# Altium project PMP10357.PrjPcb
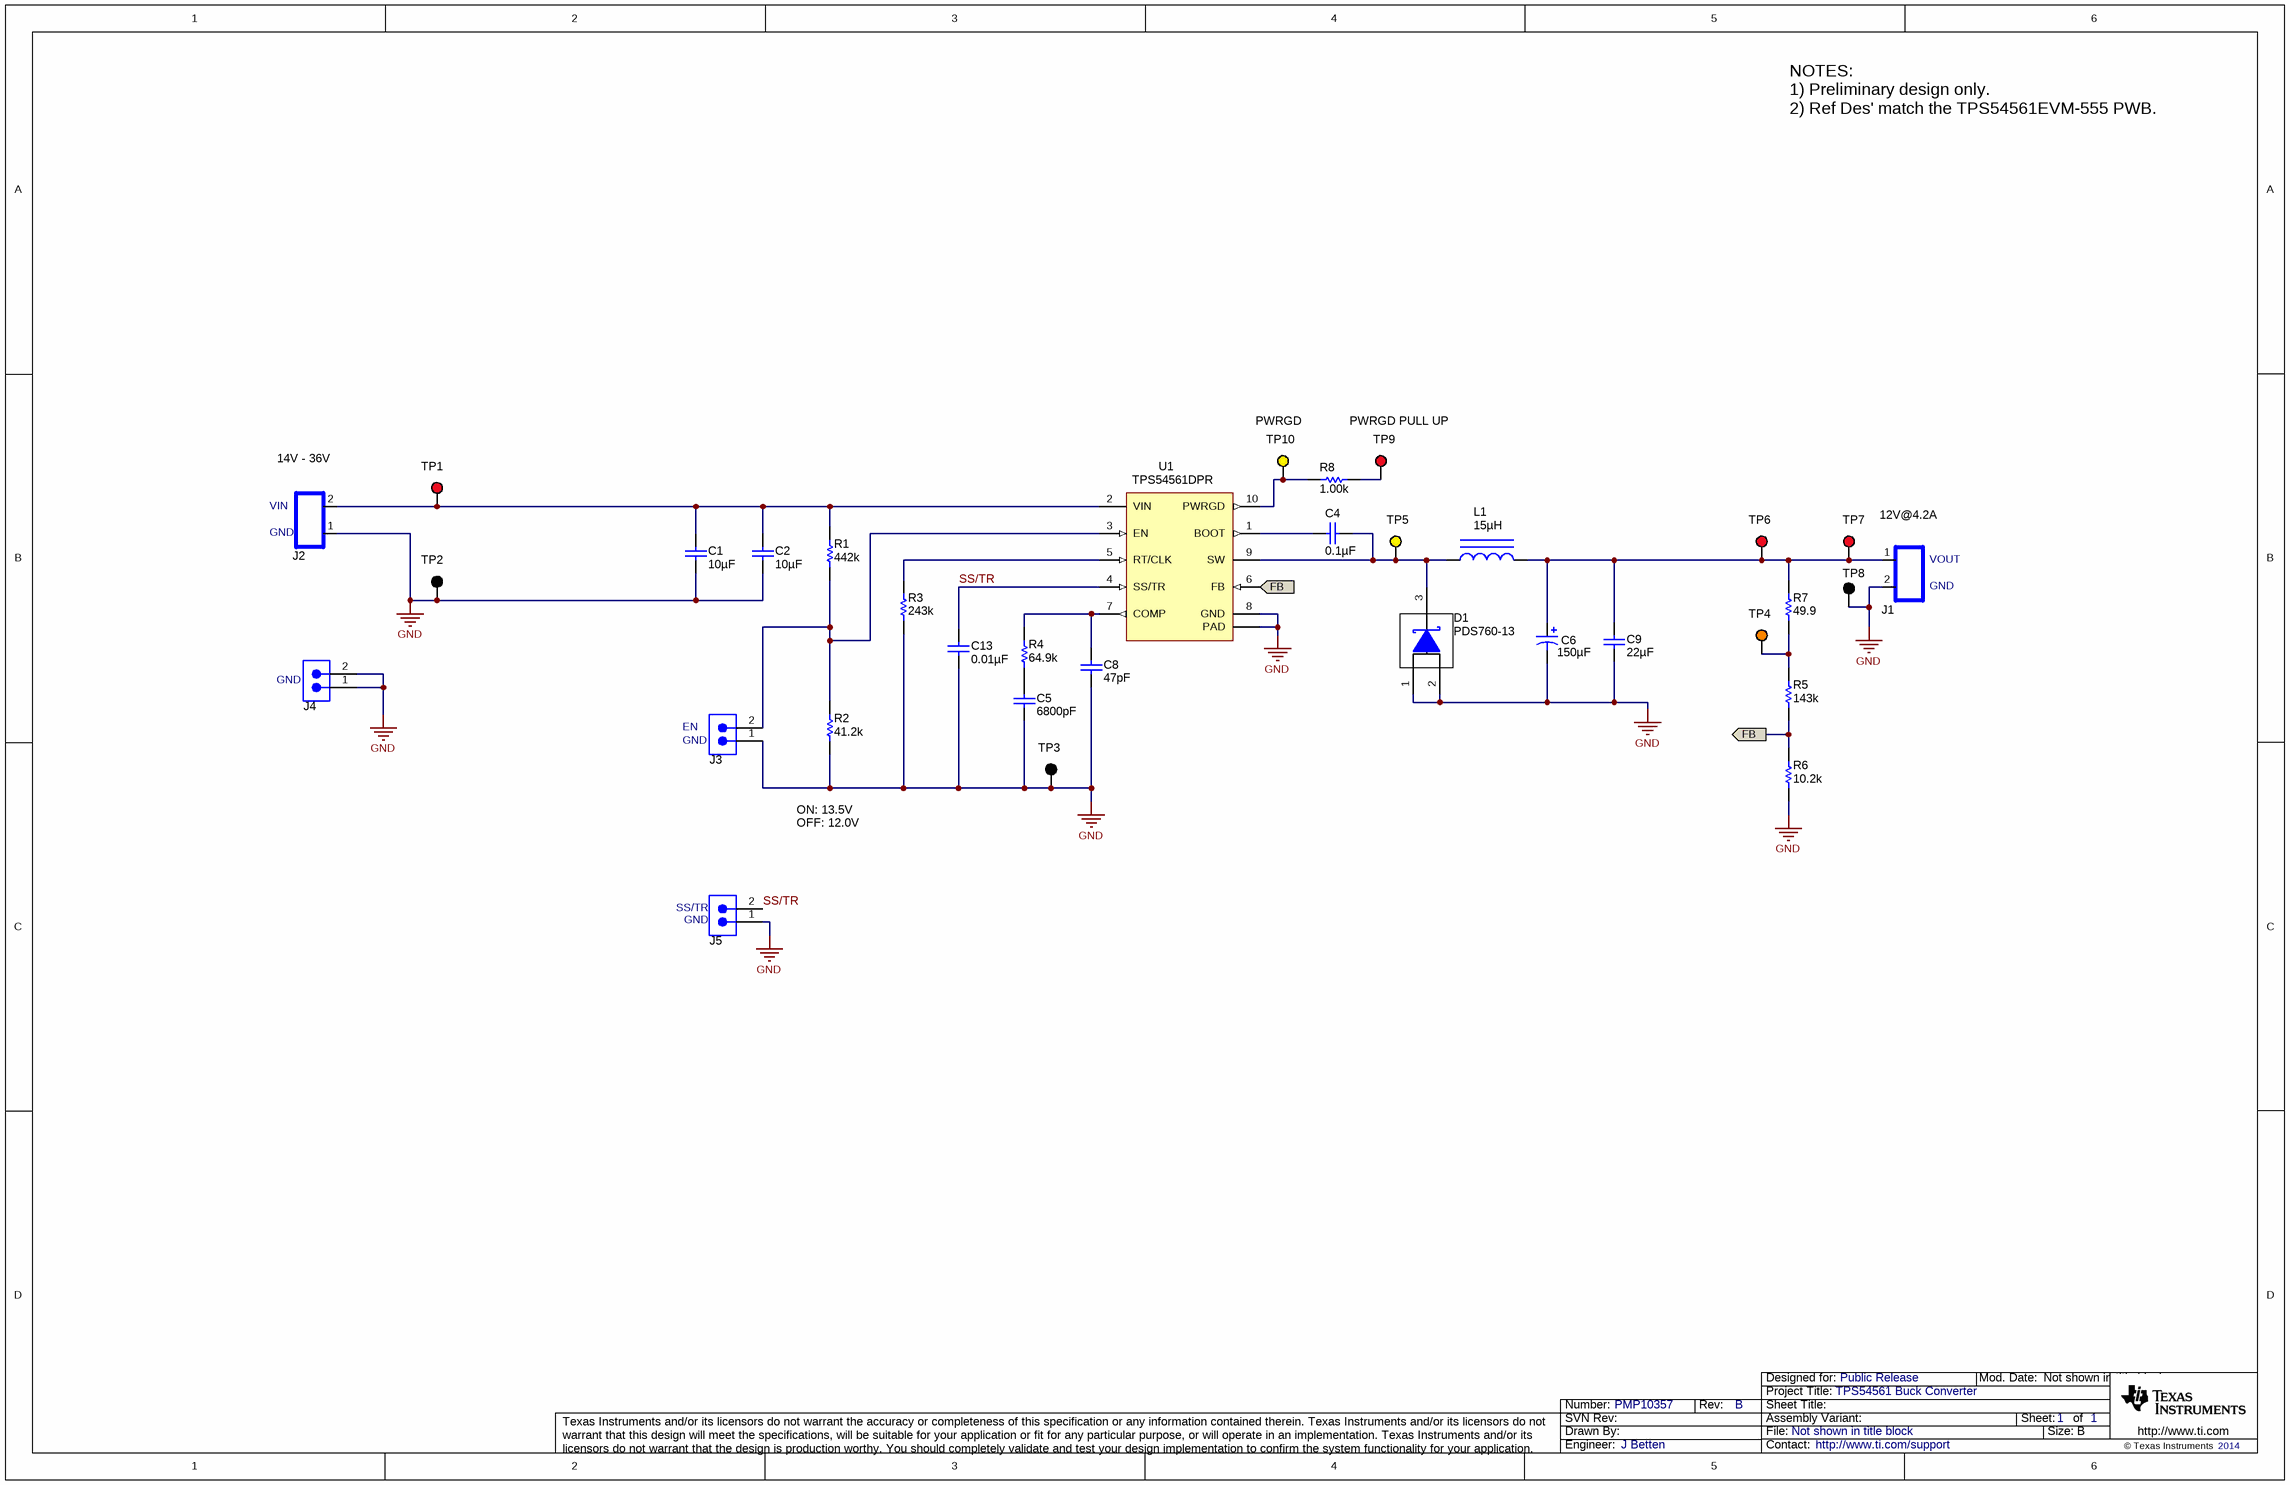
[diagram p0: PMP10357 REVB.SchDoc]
TechSupport: http://www.ti.com/support; SCH_Rev: B; PRJ_Title: TPS54561 Buck Converter; PRJ_Number: PMP10357; PRJ_Engineer: J Betten; PRJ_Customer: Public Release; PCB_Rev: A; PCB_Layout: J Betten; CopyrightYear: 2014
1 sheet, 34 parts. Net scope: flat (ports and power ports of the same name join across sheets).
Board file: PWR555A_pcb_ASCII.PcbDoc

## Sheet PMP10357 REVB.SchDoc
size 431 x 279 mm; Date: Not shown in title block; ApprovedBy: Not shown in title block; CheckedBy: Not shown in title block; Author: Not shown in title block; CompanyName: Not shown in title block; Engineer: Not shown in title block; Organization: Not shown in title block; Address1: Not shown in title block; Address2: Not shown in title block; Address3: Not shown in title block; Address4: Not shown in title block; DocumentNumber: 1; Revision: Use project parameter SCH_Rev; SheetNumber: 1; SheetTotal: 1; PageSetup: Record=PageOptions|CenterHorizontal=True|CenterVertical=True|PrintScale=1.00|XCorrection=1.00|YCorrection=1.00|PrintKind=0|BorderSize=5000000|LeftOffset=0|BottomOffset=0|Orientation=2|PaperLength=1000|PaperWidth=1000|Scale=100|PaperSource=15|PrintQuality=600|MediaType=1|DitherType=10|PaperKind=Letter|PrintScaleMode=1

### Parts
C1  ValueDisplayed: 10µF  [1210]  (hidden comment: C3225X7R1H106M250AC)
C2  ValueDisplayed: 10µF  [1210]  (hidden comment: C3225X7R1H106M250AC)
C4  ValueDisplayed: 0.1µF  [0603]  (hidden comment: C0603C104K8RACTU)
C5  ValueDisplayed: 6800pF  [0603]  (hidden comment: C1608C0G1H682J)
C6  ValueDisplayed: 150µF  [7343-20]  (hidden comment: 16TQC150MYF)
C8  ValueDisplayed: 47pF  [0603]  (hidden comment: C1608C0G1H470J)
C9  ValueDisplayed: 22µF  [1210]  (hidden comment: C3225X7R1C226M250AC)
C13  ValueDisplayed: 0.01µF  [0603]  (hidden comment: C0603C103K5RACTU)
D1  PDS760-13  [PowerDI5]
J1  TBLK_15A_2X5.1MM  [TB_2X5.1MM]  (value not drawn)
J2  TBLK_15A_2X5.1MM  [TB_2X5.1MM]  (value not drawn)
J3  TSW-102-07-G-S  [TSW-102-07-G-S]  (value not drawn)
J4  TSW-102-07-G-S  [TSW-102-07-G-S]  (value not drawn)
J5  TSW-102-07-G-S  [TSW-102-07-G-S]  (value not drawn)
L1  ValueDisplayed: 15µH  [XAL1010]  (hidden comment: XAL1010-153MEB)
R1  value 442k  [0603]  (hidden comment: CRCW0603442KFKEA)
R2  value 41.2k  [0603]  (hidden comment: CRCW060341K2FKEA)
R3  value 243k  [0603]  (hidden comment: CRCW0603243KFKEA)
R4  value 64.9k  [0603]  (hidden comment: CRCW060364K9FKEA)
R5  value 143k  [0603]  (hidden comment: CRCW0603143KFKEA)
R6  value 10.2k  [0603]  (hidden comment: CRCW060310K2FKEA)
R7  value 49.9  [0603]  (hidden comment: CRCW060349R9FKEA)
R8  value 1.00k  [0603]  (hidden comment: CRCW06031K00FKEA)
TP1  5010  [Keystone5010]  (value not drawn)
TP2  5011  [Keystone5011]  (value not drawn)
TP3  5011  [Keystone5011]  (value not drawn)
TP4  5013  [Keystone5013]  (value not drawn)
TP5  5014  [Keystone5014]  (value not drawn)
TP6  5010  [Keystone5010]  (value not drawn)
TP7  5010  [Keystone5010]  (value not drawn)
TP8  5011  [Keystone5011]  (value not drawn)
TP9  5010  [Keystone5010]  (value not drawn)
TP10  5014  [Keystone5014]  (value not drawn)
U1  TPS54561DPR  [DPR0010A]

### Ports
FB (in), FB (out)

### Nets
GND: C1.2 C2.2 C5.2 C6.2(-) C8.2 C9.2 C13.2 D1.1(A) D1.2(A) J1.2 J2.1 J3.1 J4.1 J4.2 J5.1 R2.1 R3.1 R6.1 TP2.1 TP3.1 TP8.1 U1.8(GND) U1.11(PAD)
FB: R5.1 R6.2 U1.6(FB) ; port FB
SS/TR: C13.1 J5.2 U1.4(SS/TR)
NetC1_1: C1.1 C2.1 J2.2 R1.2 TP1.1 U1.2(VIN)
NetC4_1: C4.1 D1.3(K) L1.1 TP5.1 U1.9(SW)
NetC4_2: C4.2 U1.1(BOOT)
NetC5_1: C5.1 R4.1
NetC6_1: C6.1(+) C9.1 J1.1 L1.2 R7.2 TP6.1 TP7.1
NetC8_1: C8.1 R4.2 U1.7(COMP)
NetJ3_2: J3.2 R1.1 R2.2 U1.3(EN)
NetR3_2: R3.2 U1.5(RT/CLK)
NetR5_2: R5.2 R7.1 TP4.1
NetR8_1: R8.1 TP10.1 U1.10(PWRGD)
NetR8_2: R8.2 TP9.1

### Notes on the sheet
- NOTES:
  1) Preliminary design only.
  2) Ref Des' match the TPS54561EVM-555 PWB.
- PWRGD
- PWRGD PULL UP
- (near J2) 14V - 36V
- (near J2) VIN
- (near J2) GND
- 12V@4.2A
- (near J1) VOUT
- (near J1) GND
- (near J4) GND
- (near J3) EN
- (near J3) GND
- ON: 13.5V
- OFF: 12.0V
- (near J5) SS/TR
- (near J5) GND

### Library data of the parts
C1 C2 = GRM32ER72A225KA35L: CAP, CERM, 10uF, 50V, +/-10%, X7R, 1210; Manufacturer: TDK; Polarized: N; CompType: Capacitor; U/M: EA; Cap_F: 0.0000022; Tolerance_%: 10; ESR_Ohm: 0.007; Value1: 0.007 ohm; VDC_V: 50; IRMS_A: 4.4; TaMin_C: -55; TaMax_C: 125
C4 = C0603C104K8RACTU: CAP, CERM, 0.1uF, 10V, +/-10%, X7R, 0603; Manufacturer: Kemet; Polarized: N; CompType: Capacitor; U/M: EA; Cap_F: 0.0000001; Tolerance_%: 10; TaMin_C: -55; TaMax_C: 125
C5 = C1608C0G1H332J: CAP, CERM, 6800pF, 50V, +/-5%, C0G/NP0, 0603; Manufacturer: TDK; Polarized: N; CompType: Capacitor; U/M: EA; Cap_F: 0.0000000033; Tolerance_%: 5; ESR_Ohm: 0.0309; Value1: 0.0309 ohm; VDC_V: 50; TaMin_C: -55; TaMax_C: 125
C6 = 6TPE470MAZU: CAP, TQC, 150uF, 16V, +/-10%, 0.05 ohm, SMD; Manufacturer: Sanyo; Polarized: Y; CompType: Capacitor; U/M: EA; Cap_F: 0.00047; Tolerance_%: 10; VDC_V: 16; ESR_Ohm: 0.035; IRMS_A: 1.7; TaMin_C: -55; TaMax_C: 105; Cap_Case: D
C8 = C1608C0G1H470J: CAP, CERM, 47 pF, 50 V, +/- 5%, C0G/NP0, 0603; Manufacturer: TDK; Polarized: N; CompType: Capacitor; Value: 47pF; U/M: EA; Cap_F: 0.000000000047; Tolerance_%: 5; ESR_ohm: 0.22; Value1: 0.22 ohm; VDC_V: 50; Value2: 50V; TaMin_C: -55; TaMax_C: 125
C9 = GRM32ER61C476ME15L: CAP, CERM, 22uF, 16V, +/-20%, X7R, 1210; Manufacturer: TDK; Polarized: N; CompType: Capacitor; U/M: EA; Cap_F: 0.000047; Tolerance_%: 20; ESR_Ohm: 0.002; Value1: 0.002 ohm; VDC_V: 16; TaMin_C: -55; TaMax_C: 85
C13 = C0603C103K5RACTU: CAP, CERM, 0.01uF, 50V, +/-10%, X7R, 0603; Manufacturer: Kemet; Polarized: N; CompType: Capacitor; U/M: EA; Cap_F: 0.00000001; Tolerance_%: 10; Value1: Unknown; VDC_V: 50; TaMin_C: -55; TaMax_C: 125
D1 = PDS560-13: Diode, Schottky, 60V, 7A, PowerDI5; Manufacturer: Diodes Inc.; U/M: EA; Vf_V: 0.56; Io_A: 7; Vr_V: 60; Value2: 0.56V; TJmax_C: 150
J1 J2 = TBLK_15A_2X5.1MM: Terminal Block, 2-pin, 15-A, 5.1mm; Manufacturer: OST; PartNumber: ED120/2DS; Alternate Manufacturer: Any; Alternate PartNumber: Equivalent; area: 141600; Value: ED120/2DS
J3-J5 = TSW-102-07-G-S: Header, TH, 100mil, 2x1, Gold plated, 230 mil above insulator; Manufacturer: Samtec, Inc.; U/M: EA
L1 = XAL1010-153MEB: Inductor, Shielded, Composite, 15uH, 13.8A, 0.0169 ohm, SMD; Manufacturer: Coilcraft; Ind_H: 15.0E-6; Imax_A: 13.8; Irms: 13.8A @ 40C rise; Isat: 15.5A @ 30% inductance drop; DCR_ohm: 0.02
R1 = CRCW0603442KFKEA: RES, 442k ohm, 1%, 0.1W, 0603; Manufacturer: Vishay-Dale; Alternate Manufacturer: Any; Alternate PartNumber: Equivalent; CompType: Resistor; Res_ohm: 442000; Tolerance_%: 1; Power_W: 0.1; VDC_V: 75; TempCo: 100 ppm/C; EIA_Code: E96; U/M: EA
R2 = CRCW060341K2FKEA: RES, 41.2k ohm, 1%, 0.1W, 0603; Manufacturer: Vishay-Dale; CompType: Resistor; Res_ohm: 41200; Value_Code: 41k2; Tolerance_%: 1; Power_W: 0.1; VDC_V: 75; TempCo: 100 ppm/C; EIA_Code: E96; U/M: EA
R3 = CRCW0603243KFKEA: RES, 243k ohm, 1%, 0.1W, 0603; Manufacturer: Vishay-Dale; Alternate Manufacturer: Any; Alternate PartNumber: Equivalent; CompType: Resistor; Res_ohm: 243000; Tolerance_%: 1; Power_W: 0.1; VDC_V: 75; TempCo: 100 ppm/C; EIA_Code: E96; U/M: EA
R4 = CRCW060364K9FKEA: RES, 64.9k ohm, 1%, 0.1W, 0603; Manufacturer: Vishay-Dale; CompType: Resistor; Res_ohm: 64900; Value_Code: 64k9; Tolerance_%: 1; Power_W: 0.1; VDC_V: 75; TempCo: 100 ppm/C; EIA_Code: E96; U/M: EA
R5 = CRCW0603143KFKEA: RES, 143k ohm, 1%, 0.1W, 0603; Manufacturer: Vishay-Dale; CompType: Resistor; Res_ohm: 143000; Tolerance_%: 1; Power_W: 0.1; VDC_V: 75; TempCo: 100 ppm/C; EIA_Code: E96; U/M: EA
R6 = CRCW060310K2FKEA: RES, 10.2k ohm, 1%, 0.1W, 0603; Manufacturer: Vishay-Dale; Alternate Manufacturer: Any; Alternate PartNumber: Equivalent; CompType: Resistor; Res_ohm: 10200; Value_Code: 10k2; Tolerance_%: 1; Power_W: 0.1; VDC_V: 75; TempCo: 100 ppm/C; EIA_Code: E96; U/M: EA
R7 = CRCW060349R9FKEA: RES, 49.9 ohm, 1%, 0.1W, 0603; Manufacturer: Vishay-Dale; Alternate Manufacturer: Any; Alternate PartNumber: Equivalent; CompType: Resistor; Value_Code: 49R9; Tolerance_%: 1; Power_W: 0.1; VDC_V: 75; TempCo: 100 ppm/C; EIA_Code: E96; U/M: EA
R8 = CRCW06031K00FKEA: RES, 1.00k ohm, 1%, 0.1W, 0603; Manufacturer: Vishay-Dale; CompType: Resistor; Res_ohm: 1000; Value_Code: 1k00; Tolerance_%: 1; Power_W: 0.1; VDC_V: 75; TempCo: 100 ppm/C; EIA_Code: E96; U/M: EA
TP1 TP6 TP7 TP9 = 5010: Test Point, TH, Multipurpose, Red; Manufacturer: Keystone; CompType: Test Point Loop; U/M: EA
TP2 TP3 TP8 = 5011: Test Point, TH, Multipurpose, Black; Manufacturer: Keystone; CompType: Test Point Loop; U/M: EA
TP4 = 5013: Test Point, TH, Multipurpose, Orange; Manufacturer: Keystone; CompType: Test Point Loop; U/M: EA
TP5 TP10 = 5014: Test Point, TH Multipurpose, Yellow; Manufacturer: Keystone; CompType: Test Point Loop; U/M: EA
U1 = TPS54561DPR: 60 V Input, 5 A, Step Down DC-DC Converter with Soft-Start and Eco-mode, DPR0010A; Alternate Manufacturer: None; Manufacturer: Texas Instruments; SymbolCreator: a0411947; CompType: IC; U/M: EA

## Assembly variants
001: not fitted FID1 FID2 FID3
